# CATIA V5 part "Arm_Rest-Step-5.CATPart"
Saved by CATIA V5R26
Part number: Arm_Rest
Bounding box of the stored display mesh (mm): x 743.798 to 1432.298, y -782.976 to 0, z 330.43 to 551.996
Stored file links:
  D:\LinkedIn Learning\NURBS\CATIA\Class Parts\Arm_Rest-Step-6.CATPart
  D:\LinkedIn Learning\NURBS\Arm_Rest.CATPart
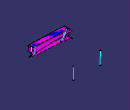
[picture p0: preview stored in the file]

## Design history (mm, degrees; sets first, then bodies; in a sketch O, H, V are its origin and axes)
AxisSystem1: origin (0, 0, 0), X (1, 0, 0), Y (0, 1, 0), Z (0, 0, 1)
StDynAnalysisRootNodeFeature1 "CATStDynAnalysisRootNodeName"
Set1 "REF DATA"
  CLDGeom1 "TOP"
  CLDGeom2 "FRONT"
  CLDGeom3 "AFT_BLEND"
  CLDGeom4 "END_AFT"
  CLDGeom5 "FORWARD_BLEND"
  CLDGeom6 "BOTTOM"
  CLDGeom7 "END_FORWARD"
  CLDGeom8 "UPPER_BLENDS"
  CLDGeom9 "LOWER_BLENDS"
  DatumSurface1 "DOOR_TRIM_SURFACE"
Set2 "FORM"
  Set3 "SLABS"
    DatumSurface2 to DatumSurface6
  Set4 "CURVES"
    St3DCurveFeature1 "CATSt3DCurveFeatureName": Order 6, CreationType 1, ClosureMode false, ConstructionPoints ({point type Coord, X 863.1168, Y 0, Z 551.1449}; {point type Coord, X 868.9503, Y 0, Z 330.43}), SymmetryMode false
    St3DCurveFeature2 "CATSt3DCurveFeatureName": Order 6, CreationType 1, ClosureMode false, ConstructionPoints ({point type Coord, X 1369.3867, Y 0, Z 551.9965}; {point type Coord, X 1358.4038, Y 0, Z 335.6826}), SymmetryMode false
    Intersect1: ToIntersect1 DatumSurface4, ToIntersect2 DatumSurface5
    Intersect2: ToIntersect1 DatumSurface6, ToIntersect2 DatumSurface4
    CurvePar1: Offset Intersect2, Support DatumSurface6, Offset2 0, Offset1 30
    CurvePar2: Offset Intersect1, Support DatumSurface5, Offset2 50, Offset1 20
    Project1: ToProject St3DCurveFeature1, Support DatumSurface4, Direction edge [YZ plane of AxisSystem1 | XY plane of AxisSystem1]
    Project2: ToProject St3DCurveFeature2, Support DatumSurface4, Direction edge [YZ plane of AxisSystem1 | XY plane of AxisSystem1]
  Set5 "BLENDS"
    Blend1: StartLimit {blendlimit Curve Project1, Support DatumSurface4, TensionValues 1.1}, EndLimit {blendlimit Curve CurvePar2, Support DatumSurface5, TensionValues 1}
    Blend2: StartLimit {blendlimit Curve CurvePar1, Support DatumSurface6, TensionValues 0.9}, EndLimit {blendlimit Curve Project2, Support DatumSurface4, TensionValues 0.8}
Body1 (main body)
